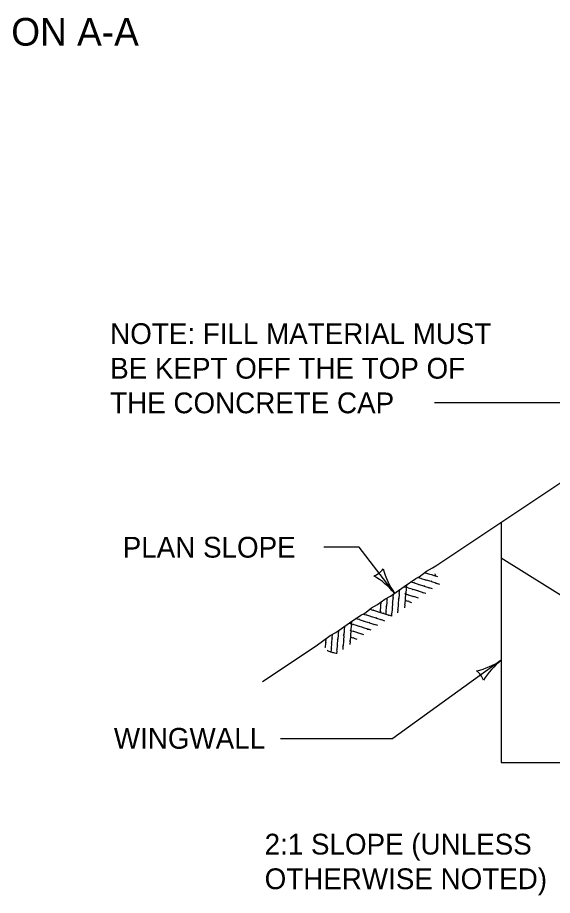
# Model space of a CAD drawing. Extents: x 49991.4 to 50021, y 49987.6 to 50011.4.
# Drawn here: x 50004.423 to 50005.968, y 50005.682 to 50008.216 of the extents above; entities that cross this region are included whole.
import ezdxf

# ---------------------------------------------------------------- set-up
doc = ezdxf.new("R2010")
doc.units = 0
for name, color, linetype in [('Level 1', 7, 'Continuous'), ('Level 2', 7, 'Continuous'), ('Level 3', 7, 'Continuous'), ('Level 4', 7, 'Continuous')]:
    doc.layers.add(name, color=color, linetype=linetype)

msp = doc.modelspace()

# ---------------------------------------------------------------- linework, layer by layer
at = {"layer": 'Level 1'}
for p, q in [((50005.6313, 50006.6335), (50006.0307, 50006.8995)), ((50005.8202, 50006.7593), (50005.8202, 50006.6567)), ((50005.8202, 50006.6567), (50006.4201, 50006.2806)), ((50005.1307, 50006.2995), (50005.2853, 50006.4026))]:
    msp.add_line(p, q, dxfattribs=at)
for points in [[(50005.4622, 50006.5217), (50005.4838, 50006.5374), (50005.5005, 50006.546), (50005.5396, 50006.5739), (50005.5731, 50006.5966), (50005.5832, 50006.6015), (50005.604, 50006.6176), (50005.6215, 50006.6278), (50005.6313, 50006.6335)], [(50005.6365, 50006.6016), (50005.625, 50006.6053), (50005.6232, 50006.6046), (50005.622, 50006.6061), (50005.61, 50006.6097), (50005.6092, 50006.6115), (50005.6076, 50006.6104), (50005.5987, 50006.6134)], [(50005.6214, 50006.5665), (50005.6122, 50006.5697), (50005.6111, 50006.5684), (50005.6105, 50006.5698), (50005.5985, 50006.5736), (50005.5978, 50006.5755), (50005.5961, 50006.5746), (50005.5838, 50006.5786), (50005.5821, 50006.578), (50005.5809, 50006.5794), (50005.5689, 50006.5831), (50005.5681, 50006.5848), (50005.5664, 50006.5838), (50005.5581, 50006.5865)], [(50005.6423, 50006.5796), (50005.6331, 50006.5827), (50005.632, 50006.5815), (50005.6315, 50006.5829), (50005.6194, 50006.5867), (50005.6187, 50006.5886), (50005.617, 50006.5877), (50005.6048, 50006.5917), (50005.603, 50006.591), (50005.6018, 50006.5924), (50005.5898, 50006.5961), (50005.589, 50006.5978), (50005.5873, 50006.5968), (50005.579, 50006.5996)], [(50005.629, 50006.6096), (50005.6281, 50006.609), (50005.6294, 50006.6076), (50005.629, 50006.6028)], [(50005.5256, 50006.5636), (50005.5245, 50006.5537), (50005.526, 50006.5529), (50005.5247, 50006.552), (50005.5238, 50006.5394), (50005.5221, 50006.5383), (50005.5233, 50006.5369), (50005.5222, 50006.524), (50005.5233, 50006.5225), (50005.5222, 50006.521), (50005.5213, 50006.5084), (50005.5198, 50006.5073), (50005.5211, 50006.5059), (50005.5203, 50006.4972)], [(50005.6023, 50006.5531), (50005.5943, 50006.5558), (50005.5932, 50006.5545), (50005.5927, 50006.556), (50005.5806, 50006.5598), (50005.5799, 50006.5616), (50005.5782, 50006.5607), (50005.566, 50006.5647), (50005.5642, 50006.5641), (50005.563, 50006.5655), (50005.551, 50006.5692), (50005.5502, 50006.5709), (50005.5485, 50006.5699), (50005.5389, 50006.5731)], [(50005.546, 50006.5782), (50005.545, 50006.5686), (50005.5465, 50006.5677), (50005.5452, 50006.5669), (50005.5442, 50006.5543), (50005.5425, 50006.5532), (50005.5438, 50006.5517), (50005.5427, 50006.5389), (50005.5437, 50006.5373), (50005.5426, 50006.5358), (50005.5417, 50006.5233), (50005.5402, 50006.5221), (50005.5416, 50006.5208), (50005.5408, 50006.512)], [(50005.4899, 50006.5405), (50005.489, 50006.5314), (50005.4905, 50006.5306), (50005.4892, 50006.5297), (50005.4882, 50006.5171), (50005.4866, 50006.516), (50005.4878, 50006.5146), (50005.4867, 50006.5017), (50005.4877, 50006.5001), (50005.4866, 50006.4986), (50005.4862, 50006.493)], [(50005.5078, 50006.5511), (50005.5068, 50006.5416), (50005.5083, 50006.5408), (50005.507, 50006.5399), (50005.506, 50006.5273), (50005.5044, 50006.5262), (50005.5056, 50006.5248), (50005.5045, 50006.5119), (50005.5055, 50006.5103), (50005.5044, 50006.5088), (50005.5036, 50006.4963), (50005.5021, 50006.4952), (50005.5034, 50006.4938), (50005.5029, 50006.4879)], [(50005.581, 50006.54), (50005.5672, 50006.5445), (50005.5654, 50006.5438), (50005.5642, 50006.5452), (50005.5522, 50006.5489), (50005.5514, 50006.5507), (50005.5497, 50006.5496), (50005.5416, 50006.5524)], [(50005.2853, 50006.4026), (50005.3254, 50006.4318), (50005.3421, 50006.4404), (50005.3812, 50006.4683), (50005.4147, 50006.491), (50005.4248, 50006.4959), (50005.4456, 50006.512), (50005.4622, 50006.5217)], [(50005.4719, 50006.5287), (50005.4708, 50006.5179), (50005.4723, 50006.5171), (50005.471, 50006.5162), (50005.47, 50006.5036), (50005.4692, 50006.503)], [(50005.562, 50006.5267), (50005.5535, 50006.5294), (50005.5527, 50006.5311), (50005.551, 50006.5301), (50005.5426, 50006.5329)], [(50005.4839, 50006.474), (50005.4747, 50006.4771), (50005.4736, 50006.4759), (50005.4731, 50006.4773), (50005.461, 50006.4811), (50005.4603, 50006.483), (50005.4586, 50006.4821), (50005.4464, 50006.4861), (50005.4446, 50006.4854), (50005.4434, 50006.4868), (50005.4314, 50006.4905), (50005.4306, 50006.4922), (50005.4289, 50006.4912), (50005.4208, 50006.4939)], [(50005.4781, 50006.496), (50005.4666, 50006.4997), (50005.4648, 50006.499), (50005.4636, 50006.5005), (50005.4516, 50006.5041), (50005.4508, 50006.5059), (50005.4492, 50006.5048), (50005.4405, 50006.5078)], [(50005.4706, 50006.504), (50005.4697, 50006.5034), (50005.471, 50006.502), (50005.4707, 50006.4984)], [(50005.504, 50006.4877), (50005.495, 50006.4908), (50005.4939, 50006.4895), (50005.4933, 50006.4909), (50005.4813, 50006.4947), (50005.4806, 50006.4966), (50005.4789, 50006.4957), (50005.4781, 50006.496)], [(50005.4439, 50006.4475), (50005.4359, 50006.4502), (50005.4348, 50006.4489), (50005.4343, 50006.4504), (50005.4222, 50006.4542), (50005.4215, 50006.456), (50005.4198, 50006.4551), (50005.4076, 50006.4591), (50005.4058, 50006.4585), (50005.4046, 50006.4599), (50005.3926, 50006.4636), (50005.3918, 50006.4653), (50005.3901, 50006.4643), (50005.3802, 50006.4676)], [(50005.3876, 50006.4726), (50005.3866, 50006.463), (50005.3881, 50006.4621), (50005.3868, 50006.4613), (50005.3858, 50006.4487), (50005.3841, 50006.4476), (50005.3854, 50006.4461), (50005.3843, 50006.4333), (50005.3853, 50006.4317), (50005.3842, 50006.4302), (50005.3833, 50006.4177), (50005.3818, 50006.4165), (50005.3832, 50006.4152), (50005.3824, 50006.4064)], [(50005.463, 50006.4609), (50005.4538, 50006.4641), (50005.4527, 50006.4628), (50005.4521, 50006.4642), (50005.4401, 50006.468), (50005.4394, 50006.4699), (50005.4377, 50006.469), (50005.4254, 50006.473), (50005.4237, 50006.4724), (50005.4225, 50006.4738), (50005.4105, 50006.4775), (50005.4097, 50006.4792), (50005.408, 50006.4782), (50005.3998, 50006.4808)], [(50005.3315, 50006.4349), (50005.3306, 50006.4258), (50005.3321, 50006.425), (50005.3308, 50006.4241), (50005.3298, 50006.4115), (50005.3282, 50006.4104), (50005.3294, 50006.409), (50005.3283, 50006.3961), (50005.3293, 50006.3945), (50005.3282, 50006.393), (50005.3275, 50006.3827)], [(50005.3495, 50006.4456), (50005.3484, 50006.436), (50005.3499, 50006.4352), (50005.3486, 50006.4343), (50005.3476, 50006.4217), (50005.346, 50006.4206), (50005.3472, 50006.4192), (50005.3461, 50006.4063), (50005.3471, 50006.4047), (50005.346, 50006.4032), (50005.3452, 50006.3907), (50005.3437, 50006.3896), (50005.345, 50006.3882), (50005.3442, 50006.3795)], [(50005.3672, 50006.4583), (50005.3661, 50006.4481), (50005.3676, 50006.4473), (50005.3663, 50006.4464), (50005.3654, 50006.4338), (50005.3637, 50006.4327), (50005.3649, 50006.4313), (50005.3638, 50006.4184), (50005.3649, 50006.4169), (50005.3638, 50006.4154), (50005.3629, 50006.4028), (50005.3614, 50006.4017), (50005.3627, 50006.4003), (50005.3619, 50006.3916)], [(50005.4226, 50006.4344), (50005.4088, 50006.4389), (50005.407, 50006.4382), (50005.4058, 50006.4396), (50005.3938, 50006.4433), (50005.393, 50006.4451), (50005.3913, 50006.444), (50005.3832, 50006.4468)], [(50005.3134, 50006.4221), (50005.3124, 50006.4123), (50005.3139, 50006.4115), (50005.3126, 50006.4106), (50005.3116, 50006.398), (50005.3108, 50006.3974)], [(50005.4036, 50006.4211), (50005.3951, 50006.4238), (50005.3943, 50006.4255), (50005.3926, 50006.4245), (50005.3842, 50006.4273)], [(50005.3426, 50006.3801), (50005.3336, 50006.3832), (50005.3325, 50006.3819), (50005.3319, 50006.3833), (50005.3199, 50006.3871), (50005.3192, 50006.389), (50005.3175, 50006.3881), (50005.3167, 50006.3884)]]:
    msp.add_lwpolyline(points, dxfattribs=at)
at = {"layer": 'Level 3'}
for p, q in [((50006.0717, 50007.1038), (50005.6267, 50007.1038)), ((50005.4096, 50006.687), (50005.3071, 50006.687)), ((50005.5118, 50006.5541), (50005.4096, 50006.687)), ((50005.8202, 50006.3609), (50005.5067, 50006.1352)), ((50005.1824, 50006.1352), (50005.5067, 50006.1352))]:
    msp.add_line(p, q, dxfattribs=at)
for centre, radius, start, end in [((50005.4336, 50006.6557), 0.0548, 289.7176, 325.44), ((50005.6935, 50006.6823), 0.2223, 195.0348, 215.2183), ((50005.3344, 50006.403), 0.233, 40.4061, 59.6559), ((50005.6978, 50006.5465), 0.2223, 283.2128, 303.3963), ((50005.9655, 50006.1788), 0.233, 128.5841, 147.8339), ((50005.7162, 50006.286), 0.0548, 17.8956, 53.618)]:
    msp.add_arc(centre, radius, start, end, dxfattribs=at)
at = {"layer": 'Level 4'}
for p, q in [((50005.8202, 50006.6567), (50005.8202, 50006.0652)), ((50005.8202, 50006.0652), (50007.0807, 50006.0652))]:
    msp.add_line(p, q, dxfattribs=at)

# ---------------------------------------------------------------- texts
at = {"layer": 'Level 2'}
for s, height, p in [('SECTION A-A', 0.08, (50004.0895, 50008.1351)), ('NOTE: FILL MATERIAL MUST', 0.06, (50004.6903, 50007.2738)), ('BE KEPT OFF THE TOP OF', 0.06, (50004.6903, 50007.1738)), ('THE CONCRETE CAP', 0.06, (50004.6903, 50007.0738)), ('PLAN SLOPE', 0.06, (50004.7266, 50006.657)), ('WINGWALL', 0.06, (50004.701, 50006.1052)), ('2:1 SLOPE (UNLESS', 0.06, (50005.1365, 50005.7998)), ('OTHERWISE NOTED)', 0.06, (50005.1365, 50005.6998))]:
    msp.add_text(s, height=height, dxfattribs=at).set_placement(p)

doc.saveas('drawing.dxf')
